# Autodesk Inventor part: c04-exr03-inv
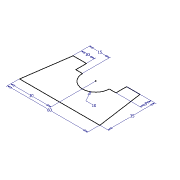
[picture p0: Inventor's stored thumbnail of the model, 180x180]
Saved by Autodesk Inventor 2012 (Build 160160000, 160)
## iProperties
Shininess: 64.0
Length Units: 11269
Angle Units: 11279
Time Units: 11290
Mass Units: 11283
Length Display Precision: 3
Angle Display Precision: 2
Compacted: True
Created: 2002-02
Part Number: c04-exr03-inv
Document SubType Name: Modeling
Density: 1 g/cm^3
Material: Default
Density: 0.0
Volumn: 0.0
Area: 0.0
PropertySet Name: Model Information
Control State: 0
Master: False
Checked Out: False
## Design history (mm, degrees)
sketch "Sketch1"
  geometry: L1 (-34.071, -15.784)-(25.929, -15.784); L2 (25.929, -15.784)-(20.929, 19.216); L3 (20.929, 19.216)-(10.929, 19.216); L4 (10.929, 19.216)-(10.929, 11.216); L5 (10.929, 11.216)-(5.929, 11.216); L6 (-14.071, 11.216)-(-19.071, 11.216); L7 (-19.071, 11.216)-(-19.071, 19.216); L8 (-19.071, 19.216)-(-29.071, 19.216); L9 (-29.071, 19.216)-(-34.071, -15.784); A1 r 10 centre (-4.071, 11.216) between (-14.071, 11.216) and (5.929, 11.216)
  constraints: 18 end point, 5 parallel, 4 equal length, 2 point on circle, 1 centre point, 1 horizontal, 1 perpendicular, 1 point on line
  dimensions: "d0" = 60 distance of L1.start L1.end; "d1" = 10 radius of A1; "d2" = 10 distance of L7.end L8.end; "d4" = 8 distance of L3.end L4.end; "d5" = 35 distance between parallel lines of L1 L3; "d6" = 30 horizontal distance of L1.start A1.centre; "d7" = 15 horizontal distance of L6.start L8.end
